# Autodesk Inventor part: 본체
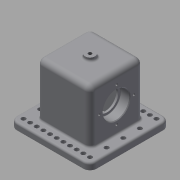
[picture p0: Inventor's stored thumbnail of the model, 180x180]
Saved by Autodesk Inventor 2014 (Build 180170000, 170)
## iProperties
Created: 2018-11
Part Number: 본체
Material: Generic
Document SubType Name: Modeling
Designer: kh
Density: 1 g/cm^3
Appearance: Default
Author: kh
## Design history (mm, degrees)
sketch "스케치1"
  geometry: L1 (-60, 60)-(60, 60); L2 (60, 60)-(60, -60); L3 (60, -60)-(-60, -60); L4 (-60, -60)-(-60, 60); L5 (-60, 60)-(60, -60); L6 (60, 60)-(-60, -60); L7 (-23, 30)-(23, 30); L8 (23, 30)-(23, -30); L9 (23, -30)-(-23, -30); L10 (-23, -30)-(-23, 30); L11 (-23, 30)-(23, -30); L12 (23, 30)-(-23, -30); 1 further point
  constraints: 24 end point, 4 midpoint, 4 parallel, 2 horizontal, 2 perpendicular
  dimensions: "d0" = 120 distance of L2.end L3.end; "d1" = 120 distance of L1.end L2.end; "d8" = 46 distance of L8.end L9.end; "d79" = 60 distance of L7.end L8.end
extrude "돌출1" new body sketch "스케치1" distance "d2" = 10; taper "d3" = 0 deg
sketch "스케치2"
  geometry: L1 (-40, 40)-(40, 40); L2 (40, 40)-(40, -40); L3 (40, -40)-(-40, -40); L4 (-40, -40)-(-40, 40); L5 (-40, 40)-(40, -40); L6 (40, 40)-(-40, -40); 1 further point
  constraints: 12 end point, 2 midpoint, 2 parallel, 1 horizontal, 1 perpendicular
  dimensions: "d4" = 80 distance of L2.end L3.end; "d5" = 80 distance of L1.end L2.end
extrude "돌출2" join sketch "스케치2" distance "d6" = 80; taper "d7" = 0 deg
extrude "돌출3" cut sketch "스케치1" distance "d9" = 80; taper "d10" = 0 deg
sketch "스케치3"
  geometry: C1 r 7.5 at (0, 0); 1 further point
  constraints: 1 centre point, 1 coincident
  dimensions: "d11" = 15 diameter of C1
extrude "돌출4" join sketch "스케치3" distance "d12" = 5; taper "d13" = 0 deg
sketch "스케치5"
  geometry: L1 (-40, 10)-(-40, 90) reference; L2 (40, 10)-(40, 90) reference; L3 (-60, 0)-(60, 0) reference; L4 (-40, 48)-(40, 48); L5 (-40, 48)-(-40, 68); L6 (-26, 68)-(-26, 64.5); L7 (-26, 64.5)-(26, 64.5); L8 (26, 64.5)-(26, 68); L9 (26, 68)-(40, 68); L10 (40, 68)-(40, 48); L11 (-40, 68)-(-26, 68); 1 further point
  constraints: 16 end point, 4 perpendicular, 4 point on line, 3 collinear, 2 parallel
  dimensions: "d16" = 48 distance between parallel lines of L4 L3; "d17" = 40 diameter of L11 L4; "d18" = 33 diameter of L7 L4; "d19" = 14 distance of L5.end L6.start
revolve "회전1" sketch "스케치5" stored, may be unused: angle "d20" = 90 deg
sketch "스케치6" dims "d21" = 52
  geometry: L1 (38, 40)-(64, 40); C1 r 20 at (38, 40) reference; 2 further points
  constraints: 2 coincident, 2 end point, 1 horizontal, 1 horizontal alignment, 2 other
hole "구멍1" sketch "스케치6" at (64, 40) diameter "d22" = 3.459; stored, may be unused: countersink angle "d26" = 90 deg, drill point angle "d28" = 118 deg; dims "d23" = 8, "d24" = 4, "d25" = 2, "d27" = 10
fillet "모깎기1" dims "d32" = 10
sketch "스케치7" dims "d38" = 10, "d45" = 10
  geometry: L1 (23, -30)-(23, 30) reference; L2 (23, 30)-(-23, 30) reference; L3 (-23, 30)-(-23, -30) reference; L4 (-23, -30)-(23, -30) reference; L5 (60, 50)-(60, -50) reference; L6 (50, -60)-(-50, -60) reference; L7 (-60, -50)-(-60, 50) reference; L8 (-50, 60)-(50, 60) reference; L9 (0, 60)-(0, -60); L10 (-60, 0)-(60, 0); A1 r 10 centre (50, 50) between (60, 50) and (50, 60) reference; A2 r 10 centre (50, -50) between (50, -60) and (60, -50) reference; A3 r 10 centre (-50, -50) between (-60, -50) and (-50, -60) reference; A4 r 10 centre (-50, 50) between (-50, 60) and (-60, 50) reference; 30 further points
  constraints: 14 symmetric about line, 4 end point, 4 midpoint, 1 coincident, 1 horizontal, 1 vertical, 14 other
  dimensions: "d35" = 10 distance of point (-50, 50) point (-40, 50); "d42" = 25 distance of point (-50, 50) point (-50, 25)
hole "구멍2" sketch "스케치7" diameter "d47" = 6.6; stored, may be unused: countersink angle "d51" = 90 deg, drill point angle "d53" = 118 deg; dims "d48" = 8, "d49" = 4, "d50" = 2, "d52" = 10
fillet "모깎기2" dims "d54" = 8
fillet "모깎기3" dims "d55" = 8, "d56" = 3
fillet "모깎기4" dims "d57" = 3, "d58" = 0.6
hole "구멍3" diameter "d61" = 5.242; stored, may be unused: countersink angle "d65" = 90 deg, drill point angle "d67" = 118 deg; dims "d59" = 10, "d60" = 10, "d62" = 8, "d63" = 4, "d64" = 2, "d66" = 10
chamfer "모따기1" distance "d68" = 1; stored, may be unused: second distance "d69" = 2, angle "d70" = 45 deg
node "작업 평면1"
sketch "스케치8"
  geometry: L1 (65.9, -43.884)-(-1.9, -43.884); L2 (-1.9, -43.884)-(-1.9, -26.116); L3 (-1.9, -26.116)-(65.9, -26.116); L4 (65.9, -26.116)-(65.9, -43.884); L5 (65.9, -35)-(-1.9, -35); L6 (32, -43.884)-(32, -26.116); L7 (32, 13)-(32, -83.758); L8 (-18, 13)-(82, 13) reference
  constraints: 6 end point, 4 midpoint, 1 collinear, 2 other
  dimensions: "d72" = 48 distance between parallel lines of L5 L8
feature "엠보싱1" sketch "스케치8" dims "d9" = 80, "d10" = 0, "d73" = 0.5, "d74" = 0
node "솔리드1"
pattern_circular "원형 패턴1" dims angle "d30" = 360 deg
mirror "대칭1"
node "투영된 루프1"
other parameters: "d71" = 25.5
